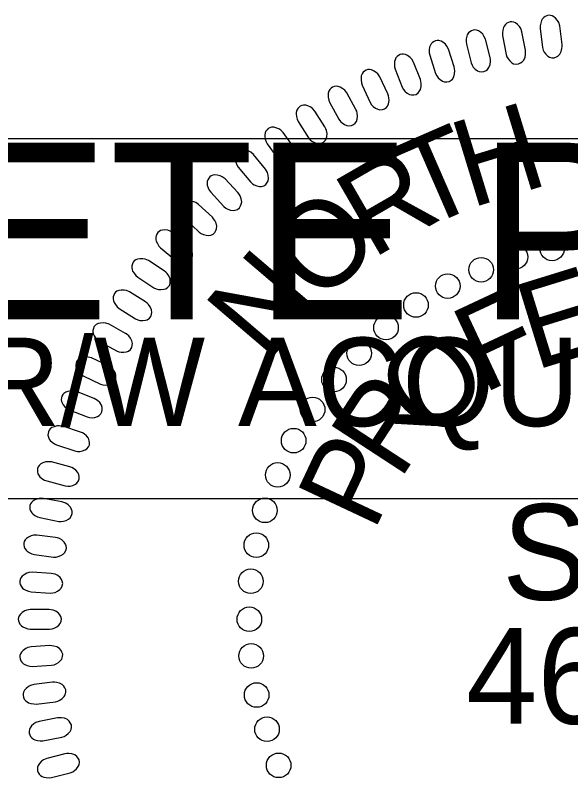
# Model space of a CAD drawing. Extents: x 505602 to 527661, y 418813 to 494436.
# Drawn here: x 507178.88 to 507215.05, y 484084.34 to 484134.03 of the extents above; entities that cross this region are included whole.
import ezdxf

# ---------------------------------------------------------------- set-up
doc = ezdxf.new("R2010")
doc.units = 0
doc.layers.add('Sheet PE Seal Cell', color=7, linetype='Continuous')
doc.layers.add('Sheet Sticker Incomplete CELL', color=7, linetype='Continuous')

msp = doc.modelspace()

# ---------------------------------------------------------------- linework, layer by layer
at = {"layer": 'Sheet PE Seal Cell'}
for points in [[(507214.482, 484132.117), (507214.328, 484133.334), (507214.264, 484133.547), (507214.194, 484133.679), (507214.062, 484133.833), (507213.952, 484133.93), (507213.831, 484133.995), (507213.722, 484134.021), (507213.608, 484134.027), (507213.499, 484133.993), (507213.384, 484133.949), (507213.288, 484133.876), (507213.196, 484133.764), (507213.147, 484133.678), (507213.099, 484133.521), (507213.062, 484133.335), (507213.06, 484133.174), (507213.21, 484131.927), (507213.253, 484131.761), (507213.315, 484131.628), (507213.424, 484131.481), (507213.553, 484131.356), (507213.659, 484131.29), (507213.822, 484131.249), (507213.973, 484131.248), (507214.116, 484131.307), (507214.214, 484131.37), (507214.328, 484131.484), (507214.425, 484131.667), (507214.469, 484131.854), (507214.483, 484131.986)], [(507212.1, 484131.749), (507211.871, 484132.953), (507211.793, 484133.162), (507211.716, 484133.29), (507211.574, 484133.435), (507211.458, 484133.525), (507211.333, 484133.582), (507211.223, 484133.602), (507211.109, 484133.601), (507211.002, 484133.56), (507210.891, 484133.508), (507210.799, 484133.43), (507210.714, 484133.312), (507210.671, 484133.222), (507210.633, 484133.063), (507210.608, 484132.876), (507210.615, 484132.715), (507210.843, 484131.479), (507210.897, 484131.316), (507210.967, 484131.187), (507211.085, 484131.048), (507211.221, 484130.931), (507211.332, 484130.871), (507211.497, 484130.842), (507211.647, 484130.851), (507211.787, 484130.918), (507211.881, 484130.986), (507211.987, 484131.108), (507212.073, 484131.296), (507212.105, 484131.486), (507212.11, 484131.618)], [(507209.795, 484131.276), (507209.491, 484132.465), (507209.4, 484132.668), (507209.314, 484132.791), (507209.164, 484132.927), (507209.042, 484133.009), (507208.914, 484133.058), (507208.802, 484133.071), (507208.689, 484133.062), (507208.585, 484133.016), (507208.477, 484132.956), (507208.39, 484132.873), (507208.314, 484132.75), (507208.276, 484132.658), (507208.247, 484132.496), (507208.234, 484132.308), (507208.252, 484132.148), (507208.557, 484130.928), (507208.621, 484130.77), (507208.699, 484130.646), (507208.826, 484130.513), (507208.969, 484130.406), (507209.083, 484130.353), (507209.25, 484130.333), (507209.4, 484130.352), (507209.535, 484130.427), (507209.624, 484130.501), (507209.722, 484130.63), (507209.795, 484130.824), (507209.816, 484131.015), (507209.813, 484131.147)], [(507207.461, 484130.656), (507207.083, 484131.823), (507206.98, 484132.02), (507206.887, 484132.136), (507206.728, 484132.263), (507206.602, 484132.338), (507206.47, 484132.379), (507206.358, 484132.385), (507206.246, 484132.369), (507206.145, 484132.316), (507206.041, 484132.25), (507205.96, 484132.161), (507205.891, 484132.034), (507205.859, 484131.939), (507205.84, 484131.776), (507205.839, 484131.587), (507205.867, 484131.428), (507206.248, 484130.231), (507206.322, 484130.076), (507206.407, 484129.958), (507206.542, 484129.833), (507206.692, 484129.735), (507206.809, 484129.689), (507206.977, 484129.681), (507207.125, 484129.708), (507207.255, 484129.792), (507207.339, 484129.872), (507207.429, 484130.006), (507207.49, 484130.204), (507207.499, 484130.395), (507207.487, 484130.528)], [(507205.261, 484129.839), (507204.809, 484130.98), (507204.694, 484131.171), (507204.594, 484131.281), (507204.427, 484131.398), (507204.297, 484131.464), (507204.163, 484131.497), (507204.051, 484131.495), (507203.94, 484131.472), (507203.843, 484131.412), (507203.742, 484131.341), (507203.667, 484131.247), (507203.606, 484131.116), (507203.58, 484131.02), (507203.572, 484130.855), (507203.583, 484130.667), (507203.621, 484130.51), (507204.076, 484129.339), (507204.159, 484129.19), (507204.253, 484129.076), (507204.395, 484128.96), (507204.55, 484128.872), (507204.67, 484128.833), (507204.838, 484128.836), (507204.984, 484128.872), (507205.108, 484128.965), (507205.187, 484129.049), (507205.269, 484129.189), (507205.318, 484129.39), (507205.314, 484129.582), (507205.295, 484129.714)], [(507203.143, 484128.907), (507202.621, 484130.017), (507202.494, 484130.199), (507202.387, 484130.304), (507202.214, 484130.41), (507202.079, 484130.467), (507201.944, 484130.492), (507201.832, 484130.483), (507201.722, 484130.454), (507201.629, 484130.388), (507201.534, 484130.31), (507201.464, 484130.212), (507201.412, 484130.077), (507201.392, 484129.979), (507201.395, 484129.815), (507201.417, 484129.627), (507201.464, 484129.473), (507201.993, 484128.333), (507202.085, 484128.189), (507202.185, 484128.081), (507202.334, 484127.976), (507202.495, 484127.897), (507202.617, 484127.866), (507202.784, 484127.879), (507202.928, 484127.924), (507203.046, 484128.024), (507203.12, 484128.113), (507203.192, 484128.257), (507203.229, 484128.462), (507203.213, 484128.653), (507203.185, 484128.783)], [(507201.06, 484127.892), (507200.469, 484128.968), (507200.331, 484129.143), (507200.218, 484129.239), (507200.038, 484129.334), (507199.9, 484129.384), (507199.764, 484129.4), (507199.653, 484129.384), (507199.545, 484129.347), (507199.456, 484129.276), (507199.366, 484129.192), (507199.303, 484129.09), (507199.259, 484128.952), (507199.245, 484128.853), (507199.258, 484128.689), (507199.292, 484128.503), (507199.349, 484128.353), (507199.948, 484127.248), (507200.049, 484127.11), (507200.156, 484127.009), (507200.311, 484126.913), (507200.477, 484126.844), (507200.6, 484126.821), (507200.767, 484126.844), (507200.907, 484126.899), (507201.019, 484127.005), (507201.087, 484127.099), (507201.15, 484127.248), (507201.173, 484127.454), (507201.146, 484127.644), (507201.109, 484127.772)], [(507199.043, 484126.751), (507198.386, 484127.787), (507198.237, 484127.952), (507198.118, 484128.042), (507197.933, 484128.126), (507197.792, 484128.166), (507197.655, 484128.173), (507197.544, 484128.151), (507197.439, 484128.107), (507197.355, 484128.031), (507197.27, 484127.941), (507197.214, 484127.835), (507197.179, 484127.695), (507197.171, 484127.595), (507197.194, 484127.433), (507197.24, 484127.249), (507197.306, 484127.102), (507197.973, 484126.037), (507198.083, 484125.906), (507198.196, 484125.812), (507198.357, 484125.725), (507198.526, 484125.667), (507198.651, 484125.652), (507198.816, 484125.686), (507198.952, 484125.749), (507199.058, 484125.862), (507199.119, 484125.961), (507199.173, 484126.113), (507199.183, 484126.32), (507199.144, 484126.508), (507199.1, 484126.633)], [(507197.042, 484125.396), (507196.321, 484126.389), (507196.162, 484126.544), (507196.038, 484126.627), (507195.847, 484126.698), (507195.704, 484126.73), (507195.567, 484126.728), (507195.458, 484126.699), (507195.356, 484126.649), (507195.277, 484126.567), (507195.198, 484126.473), (507195.149, 484126.363), (507195.122, 484126.221), (507195.121, 484126.121), (507195.155, 484125.96), (507195.211, 484125.78), (507195.287, 484125.638), (507196.019, 484124.617), (507196.137, 484124.493), (507196.255, 484124.405), (507196.421, 484124.329), (507196.594, 484124.282), (507196.72, 484124.275), (507196.882, 484124.319), (507197.015, 484124.39), (507197.112, 484124.511), (507197.167, 484124.612), (507197.212, 484124.768), (507197.209, 484124.975), (507197.158, 484125.16), (507197.106, 484125.283)], [(507195.162, 484124.007), (507194.38, 484124.953), (507194.212, 484125.098), (507194.082, 484125.172), (507193.888, 484125.231), (507193.743, 484125.254), (507193.606, 484125.244), (507193.5, 484125.208), (507193.401, 484125.152), (507193.327, 484125.065), (507193.254, 484124.966), (507193.211, 484124.853), (507193.194, 484124.709), (507193.199, 484124.61), (507193.242, 484124.451), (507193.31, 484124.275), (507193.395, 484124.137), (507194.189, 484123.165), (507194.315, 484123.048), (507194.439, 484122.969), (507194.609, 484122.904), (507194.785, 484122.867), (507194.911, 484122.868), (507195.07, 484122.922), (507195.198, 484123.002), (507195.287, 484123.128), (507195.336, 484123.232), (507195.371, 484123.39), (507195.354, 484123.597), (507195.292, 484123.778), (507195.232, 484123.898)], [(507193.374, 484122.468), (507192.535, 484123.363), (507192.357, 484123.497), (507192.223, 484123.564), (507192.025, 484123.61), (507191.88, 484123.624), (507191.744, 484123.605), (507191.64, 484123.563), (507191.544, 484123.501), (507191.476, 484123.409), (507191.409, 484123.305), (507191.374, 484123.19), (507191.366, 484123.046), (507191.377, 484122.947), (507191.43, 484122.791), (507191.51, 484122.62), (507191.602, 484122.489), (507192.457, 484121.567), (507192.589, 484121.458), (507192.717, 484121.388), (507192.892, 484121.332), (507193.07, 484121.307), (507193.195, 484121.315), (507193.35, 484121.379), (507193.473, 484121.467), (507193.554, 484121.599), (507193.597, 484121.706), (507193.622, 484121.866), (507193.593, 484122.071), (507193.518, 484122.249), (507193.452, 484122.363)], [(507191.712, 484120.859), (507190.818, 484121.699), (507190.632, 484121.822), (507190.495, 484121.879), (507190.294, 484121.914), (507190.148, 484121.918), (507190.013, 484121.891), (507189.912, 484121.842), (507189.821, 484121.774), (507189.759, 484121.679), (507189.699, 484121.571), (507189.67, 484121.454), (507189.671, 484121.309), (507189.689, 484121.211), (507189.751, 484121.059), (507189.841, 484120.893), (507189.942, 484120.767), (507190.853, 484119.901), (507190.992, 484119.802), (507191.124, 484119.738), (507191.302, 484119.695), (507191.48, 484119.681), (507191.605, 484119.697), (507191.757, 484119.77), (507191.873, 484119.866), (507191.946, 484120.002), (507191.982, 484120.112), (507191.996, 484120.273), (507191.955, 484120.477), (507191.87, 484120.649), (507191.796, 484120.759)], [(507190.098, 484119.072), (507189.154, 484119.854), (507188.96, 484119.965), (507188.82, 484120.014), (507188.617, 484120.036), (507188.471, 484120.031), (507188.339, 484119.995), (507188.241, 484119.94), (507188.154, 484119.866), (507188.098, 484119.767), (507188.045, 484119.656), (507188.024, 484119.538), (507188.034, 484119.393), (507188.057, 484119.296), (507188.13, 484119.149), (507188.23, 484118.988), (507188.338, 484118.869), (507189.301, 484118.062), (507189.446, 484117.971), (507189.583, 484117.917), (507189.763, 484117.884), (507189.941, 484117.882), (507190.065, 484117.906), (507190.211, 484117.989), (507190.322, 484118.091), (507190.387, 484118.232), (507190.415, 484118.344), (507190.419, 484118.506), (507190.365, 484118.705), (507190.27, 484118.872), (507190.188, 484118.978)], [(507188.574, 484117.37), (507187.544, 484118.036), (507187.339, 484118.123), (507187.193, 484118.155), (507186.99, 484118.153), (507186.845, 484118.131), (507186.718, 484118.08), (507186.628, 484118.014), (507186.55, 484117.93), (507186.505, 484117.825), (507186.466, 484117.708), (507186.459, 484117.588), (507186.486, 484117.446), (507186.52, 484117.353), (507186.61, 484117.215), (507186.728, 484117.067), (507186.85, 484116.962), (507187.901, 484116.274), (507188.056, 484116.2), (507188.197, 484116.162), (507188.38, 484116.151), (507188.558, 484116.17), (507188.678, 484116.208), (507188.813, 484116.307), (507188.911, 484116.422), (507188.959, 484116.569), (507188.974, 484116.684), (507188.959, 484116.845), (507188.882, 484117.037), (507188.767, 484117.191), (507188.674, 484117.287)], [(507187.359, 484115.347), (507186.324, 484116.004), (507186.119, 484116.09), (507185.973, 484116.122), (507185.769, 484116.118), (507185.625, 484116.094), (507185.497, 484116.043), (507185.408, 484115.976), (507185.33, 484115.891), (507185.287, 484115.786), (507185.249, 484115.669), (507185.243, 484115.549), (507185.271, 484115.407), (507185.306, 484115.314), (507185.397, 484115.176), (507185.516, 484115.03), (507185.639, 484114.926), (507186.696, 484114.246), (507186.851, 484114.174), (507186.993, 484114.136), (507187.175, 484114.127), (507187.353, 484114.147), (507187.473, 484114.186), (507187.607, 484114.287), (507187.704, 484114.402), (507187.751, 484114.549), (507187.765, 484114.664), (507187.749, 484114.826), (507187.67, 484115.017), (507187.554, 484115.17), (507187.461, 484115.265)], [(507186.056, 484113.298), (507184.981, 484113.889), (507184.771, 484113.962), (507184.623, 484113.984), (507184.421, 484113.967), (507184.277, 484113.935), (507184.154, 484113.875), (507184.069, 484113.803), (507183.997, 484113.714), (507183.961, 484113.606), (507183.929, 484113.487), (507183.931, 484113.367), (507183.968, 484113.227), (507184.009, 484113.136), (507184.107, 484113.005), (507184.236, 484112.866), (507184.365, 484112.769), (507185.462, 484112.157), (507185.621, 484112.095), (507185.765, 484112.067), (507185.949, 484112.069), (507186.125, 484112.099), (507186.242, 484112.146), (507186.37, 484112.255), (507186.459, 484112.377), (507186.496, 484112.527), (507186.503, 484112.642), (507186.477, 484112.802), (507186.386, 484112.988), (507186.262, 484113.133), (507186.162, 484113.222)], [(507184.947, 484111.174), (507183.837, 484111.696), (507183.623, 484111.757), (507183.474, 484111.769), (507183.273, 484111.739), (507183.132, 484111.698), (507183.013, 484111.631), (507182.932, 484111.553), (507182.866, 484111.46), (507182.836, 484111.35), (507182.813, 484111.229), (507182.822, 484111.109), (507182.868, 484110.972), (507182.914, 484110.884), (507183.021, 484110.759), (507183.158, 484110.628), (507183.292, 484110.54), (507184.427, 484109.998), (507184.589, 484109.946), (507184.735, 484109.928), (507184.917, 484109.94), (507185.091, 484109.983), (507185.205, 484110.036), (507185.326, 484110.153), (507185.408, 484110.28), (507185.435, 484110.432), (507185.435, 484110.548), (507185.399, 484110.705), (507185.297, 484110.886), (507185.163, 484111.023), (507185.058, 484111.105)], [(507184.008, 484109.055), (507182.868, 484109.507), (507182.65, 484109.553), (507182.501, 484109.556), (507182.302, 484109.514), (507182.164, 484109.464), (507182.049, 484109.389), (507181.973, 484109.306), (507181.913, 484109.21), (507181.89, 484109.098), (507181.874, 484108.976), (507181.891, 484108.857), (507181.945, 484108.723), (507181.997, 484108.637), (507182.112, 484108.52), (507182.257, 484108.399), (507182.396, 484108.319), (507183.562, 484107.849), (507183.727, 484107.807), (507183.874, 484107.798), (507184.055, 484107.822), (507184.226, 484107.875), (507184.337, 484107.936), (507184.451, 484108.06), (507184.524, 484108.191), (507184.542, 484108.344), (507184.534, 484108.461), (507184.488, 484108.616), (507184.374, 484108.789), (507184.232, 484108.918), (507184.122, 484108.993)], [(507183.132, 484106.866), (507181.965, 484107.245), (507181.745, 484107.277), (507181.596, 484107.271), (507181.4, 484107.217), (507181.265, 484107.158), (507181.155, 484107.076), (507181.085, 484106.99), (507181.032, 484106.889), (507181.016, 484106.776), (507181.007, 484106.653), (507181.032, 484106.535), (507181.094, 484106.405), (507181.152, 484106.323), (507181.273, 484106.212), (507181.425, 484106.101), (507181.57, 484106.03), (507182.763, 484105.633), (507182.931, 484105.603), (507183.078, 484105.603), (507183.257, 484105.638), (507183.424, 484105.702), (507183.531, 484105.769), (507183.636, 484105.9), (507183.701, 484106.036), (507183.709, 484106.191), (507183.694, 484106.305), (507183.639, 484106.458), (507183.515, 484106.623), (507183.364, 484106.743), (507183.25, 484106.812)], [(507182.428, 484104.61), (507181.239, 484104.916), (507181.018, 484104.934), (507180.869, 484104.919), (507180.677, 484104.852), (507180.547, 484104.785), (507180.441, 484104.697), (507180.377, 484104.605), (507180.329, 484104.501), (507180.321, 484104.388), (507180.32, 484104.264), (507180.352, 484104.148), (507180.423, 484104.022), (507180.485, 484103.944), (507180.613, 484103.841), (507180.772, 484103.74), (507180.921, 484103.678), (507182.136, 484103.357), (507182.306, 484103.337), (507182.452, 484103.346), (507182.629, 484103.393), (507182.792, 484103.467), (507182.894, 484103.541), (507182.991, 484103.678), (507183.047, 484103.818), (507183.046, 484103.972), (507183.024, 484104.087), (507182.959, 484104.235), (507182.825, 484104.392), (507182.667, 484104.502), (507182.549, 484104.563)], [(507181.916, 484102.314), (507180.712, 484102.545), (507180.489, 484102.549), (507180.342, 484102.525), (507180.154, 484102.446), (507180.028, 484102.371), (507179.929, 484102.276), (507179.87, 484102.181), (507179.829, 484102.075), (507179.828, 484101.961), (507179.835, 484101.837), (507179.874, 484101.724), (507179.952, 484101.602), (507180.019, 484101.528), (507180.154, 484101.434), (507180.319, 484101.341), (507180.471, 484101.289), (507181.705, 484101.046), (507181.875, 484101.037), (507182.021, 484101.055), (507182.194, 484101.112), (507182.352, 484101.196), (507182.449, 484101.277), (507182.537, 484101.42), (507182.585, 484101.563), (507182.574, 484101.718), (507182.544, 484101.829), (507182.47, 484101.973), (507182.327, 484102.122), (507182.162, 484102.222), (507182.041, 484102.276)], [(507181.496, 484100), (507180.279, 484100.154), (507180.057, 484100.145), (507179.911, 484100.111), (507179.729, 484100.021), (507179.608, 484099.938), (507179.515, 484099.837), (507179.462, 484099.738), (507179.428, 484099.629), (507179.434, 484099.516), (507179.449, 484099.393), (507179.495, 484099.282), (507179.581, 484099.166), (507179.653, 484099.096), (507179.792, 484099.01), (507179.963, 484098.929), (507180.118, 484098.886), (507181.364, 484098.721), (507181.535, 484098.722), (507181.679, 484098.749), (507181.848, 484098.818), (507182.001, 484098.912), (507182.093, 484098.999), (507182.172, 484099.146), (507182.211, 484099.293), (507182.189, 484099.445), (507182.153, 484099.556), (507182.07, 484099.694), (507181.917, 484099.834), (507181.747, 484099.924), (507181.623, 484099.969)], [(507181.21, 484097.656), (507179.985, 484097.734), (507179.764, 484097.71), (507179.621, 484097.667), (507179.445, 484097.566), (507179.329, 484097.476), (507179.242, 484097.369), (507179.196, 484097.267), (507179.169, 484097.156), (507179.182, 484097.043), (507179.205, 484096.922), (507179.257, 484096.814), (507179.35, 484096.703), (507179.426, 484096.638), (507179.571, 484096.561), (507179.746, 484096.49), (507179.904, 484096.458), (507181.158, 484096.371), (507181.329, 484096.383), (507181.471, 484096.419), (507181.636, 484096.499), (507181.782, 484096.601), (507181.868, 484096.693), (507181.937, 484096.846), (507181.967, 484096.994), (507181.936, 484097.146), (507181.893, 484097.254), (507181.802, 484097.387), (507181.64, 484097.517), (507181.465, 484097.596), (507181.338, 484097.633)], [(507181.08, 484095.305), (507179.853, 484095.306), (507179.634, 484095.268), (507179.493, 484095.217), (507179.324, 484095.104), (507179.214, 484095.007), (507179.135, 484094.895), (507179.095, 484094.79), (507179.075, 484094.678), (507179.095, 484094.566), (507179.124, 484094.447), (507179.184, 484094.342), (507179.284, 484094.237), (507179.364, 484094.177), (507179.513, 484094.11), (507179.693, 484094.05), (507179.852, 484094.028), (507181.109, 484094.02), (507181.278, 484094.042), (507181.418, 484094.087), (507181.577, 484094.177), (507181.717, 484094.289), (507181.797, 484094.386), (507181.857, 484094.543), (507181.877, 484094.693), (507181.837, 484094.842), (507181.787, 484094.946), (507181.688, 484095.074), (507181.518, 484095.193), (507181.339, 484095.26), (507181.209, 484095.291)], [(507181.132, 484092.948), (507179.907, 484092.871), (507179.691, 484092.82), (507179.555, 484092.76), (507179.392, 484092.637), (507179.288, 484092.533), (507179.216, 484092.416), (507179.183, 484092.309), (507179.171, 484092.196), (507179.198, 484092.086), (507179.235, 484091.968), (507179.3, 484091.867), (507179.407, 484091.769), (507179.49, 484091.714), (507179.644, 484091.657), (507179.827, 484091.608), (507179.987, 484091.596), (507181.242, 484091.667), (507181.41, 484091.7), (507181.546, 484091.753), (507181.7, 484091.853), (507181.832, 484091.973), (507181.906, 484092.075), (507181.956, 484092.235), (507181.966, 484092.386), (507181.917, 484092.533), (507181.861, 484092.634), (507181.753, 484092.755), (507181.577, 484092.863), (507181.393, 484092.92), (507181.262, 484092.941)], [(507181.297, 484090.567), (507180.079, 484090.414), (507179.867, 484090.349), (507179.734, 484090.28), (507179.58, 484090.147), (507179.483, 484090.037), (507179.418, 484089.916), (507179.392, 484089.807), (507179.386, 484089.693), (507179.42, 484089.585), (507179.465, 484089.47), (507179.537, 484089.373), (507179.649, 484089.282), (507179.736, 484089.232), (507179.892, 484089.184), (507180.078, 484089.147), (507180.239, 484089.145), (507181.487, 484089.295), (507181.652, 484089.338), (507181.785, 484089.401), (507181.932, 484089.509), (507182.057, 484089.637), (507182.124, 484089.744), (507182.164, 484089.907), (507182.164, 484090.058), (507182.106, 484090.202), (507182.044, 484090.299), (507181.929, 484090.413), (507181.746, 484090.51), (507181.559, 484090.554), (507181.427, 484090.568)], [(507181.63, 484088.241), (507180.425, 484088.012), (507180.216, 484087.934), (507180.089, 484087.857), (507179.943, 484087.715), (507179.853, 484087.599), (507179.796, 484087.474), (507179.777, 484087.364), (507179.778, 484087.25), (507179.819, 484087.144), (507179.871, 484087.032), (507179.948, 484086.94), (507180.067, 484086.856), (507180.156, 484086.812), (507180.316, 484086.773), (507180.503, 484086.748), (507180.664, 484086.756), (507181.9, 484086.984), (507182.062, 484087.038), (507182.191, 484087.108), (507182.33, 484087.226), (507182.447, 484087.362), (507182.507, 484087.473), (507182.537, 484087.638), (507182.528, 484087.789), (507182.461, 484087.928), (507182.393, 484088.022), (507182.271, 484088.127), (507182.082, 484088.213), (507181.892, 484088.246), (507181.76, 484088.25)], [(507182.11, 484085.9), (507180.921, 484085.596), (507180.718, 484085.505), (507180.595, 484085.42), (507180.459, 484085.269), (507180.377, 484085.147), (507180.328, 484085.019), (507180.315, 484084.908), (507180.324, 484084.794), (507180.371, 484084.691), (507180.429, 484084.582), (507180.513, 484084.496), (507180.636, 484084.419), (507180.728, 484084.381), (507180.89, 484084.353), (507181.079, 484084.34), (507181.239, 484084.357), (507182.458, 484084.662), (507182.617, 484084.726), (507182.74, 484084.804), (507182.873, 484084.931), (507182.98, 484085.074), (507183.033, 484085.187), (507183.052, 484085.355), (507183.034, 484085.505), (507182.959, 484085.639), (507182.884, 484085.729), (507182.756, 484085.827), (507182.562, 484085.9), (507182.371, 484085.922), (507182.239, 484085.918)]]:
    msp.add_lwpolyline(points, close=True, dxfattribs=at)
for centre in [(507213.835, 484118.835), (507211.446, 484118.278), (507209.216, 484117.442), (507207.041, 484116.381), (507204.971, 484115.147), (507203.019, 484113.674), (507201.267, 484112.001), (507199.634, 484110.289), (507198.24, 484108.337), (507197.005, 484106.306), (507195.969, 484104.075), (507195.132, 484101.765), (507194.574, 484099.495), (507194.215, 484097.144), (507194.119, 484094.67), (507194.237, 484092.28), (507194.595, 484089.73), (507195.271, 484087.499), (507196.027, 484085.148)]:
    msp.add_circle(centre, 0.801, dxfattribs=at)
at = {"layer": 'Sheet Sticker Incomplete CELL'}
msp.add_lwpolyline([(507095.597, 484102.505), (507095.597, 484126.005), (507242.597, 484126.005), (507242.597, 484102.505)], close=True, dxfattribs=at)

# ---------------------------------------------------------------- texts
at = {"layer": 'Sheet PE Seal Cell'}
for s, height, rotation, p in [('H', 5.669, 17.0557, (507208.505, 484121.439)), ('T', 5.669, 23.5451, (507205.326, 484120.03)), ('R', 5.669, 30.0345, (507202.105, 484118.111)), ('O', 5.669, 43.0132, (507198.63, 484115.082)), ('N', 5.669, 49.5025, (507195.283, 484111.327)), ('E', 5.669, 17.1686, (507212.701, 484110.87)), ('F', 5.669, 25.1084, (507209.311, 484109.332)), ('O', 5.669, 40.988, (507205.614, 484106.193)), ('R', 5.669, 56.8676, (507203.9, 484103.647)), ('P', 5.669, 64.8074, (507202.214, 484100.285)), ('SEAL', 6.2363, 359.9814, (507210.585, 484095.936)), ('46155', 6.2363, 359.9814, (507208.236, 484087.857))]:
    msp.add_text(s, height=height, rotation=rotation, dxfattribs=at).set_placement(p)
at = {"layer": 'Sheet Sticker Incomplete CELL'}
for s, height, p in [('INCOMPLETE PLANS', 11.52, (507104.547, 484114.205)), ('DO NOT USE FOR R/W ACQUISITION', 5.76, (507107.797, 484107.255))]:
    msp.add_text(s, height=height, dxfattribs=at).set_placement(p)

doc.saveas('drawing.dxf')
